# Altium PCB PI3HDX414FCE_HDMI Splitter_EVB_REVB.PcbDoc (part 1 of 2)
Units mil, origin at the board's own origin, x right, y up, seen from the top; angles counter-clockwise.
Board outline 3885 x 4772 mil, 4 copper layers (Top Layer, InternalPlane1, InternalPlane2, Bottom Layer); 85 components, 103 nets, 428 pads, 187 vias.
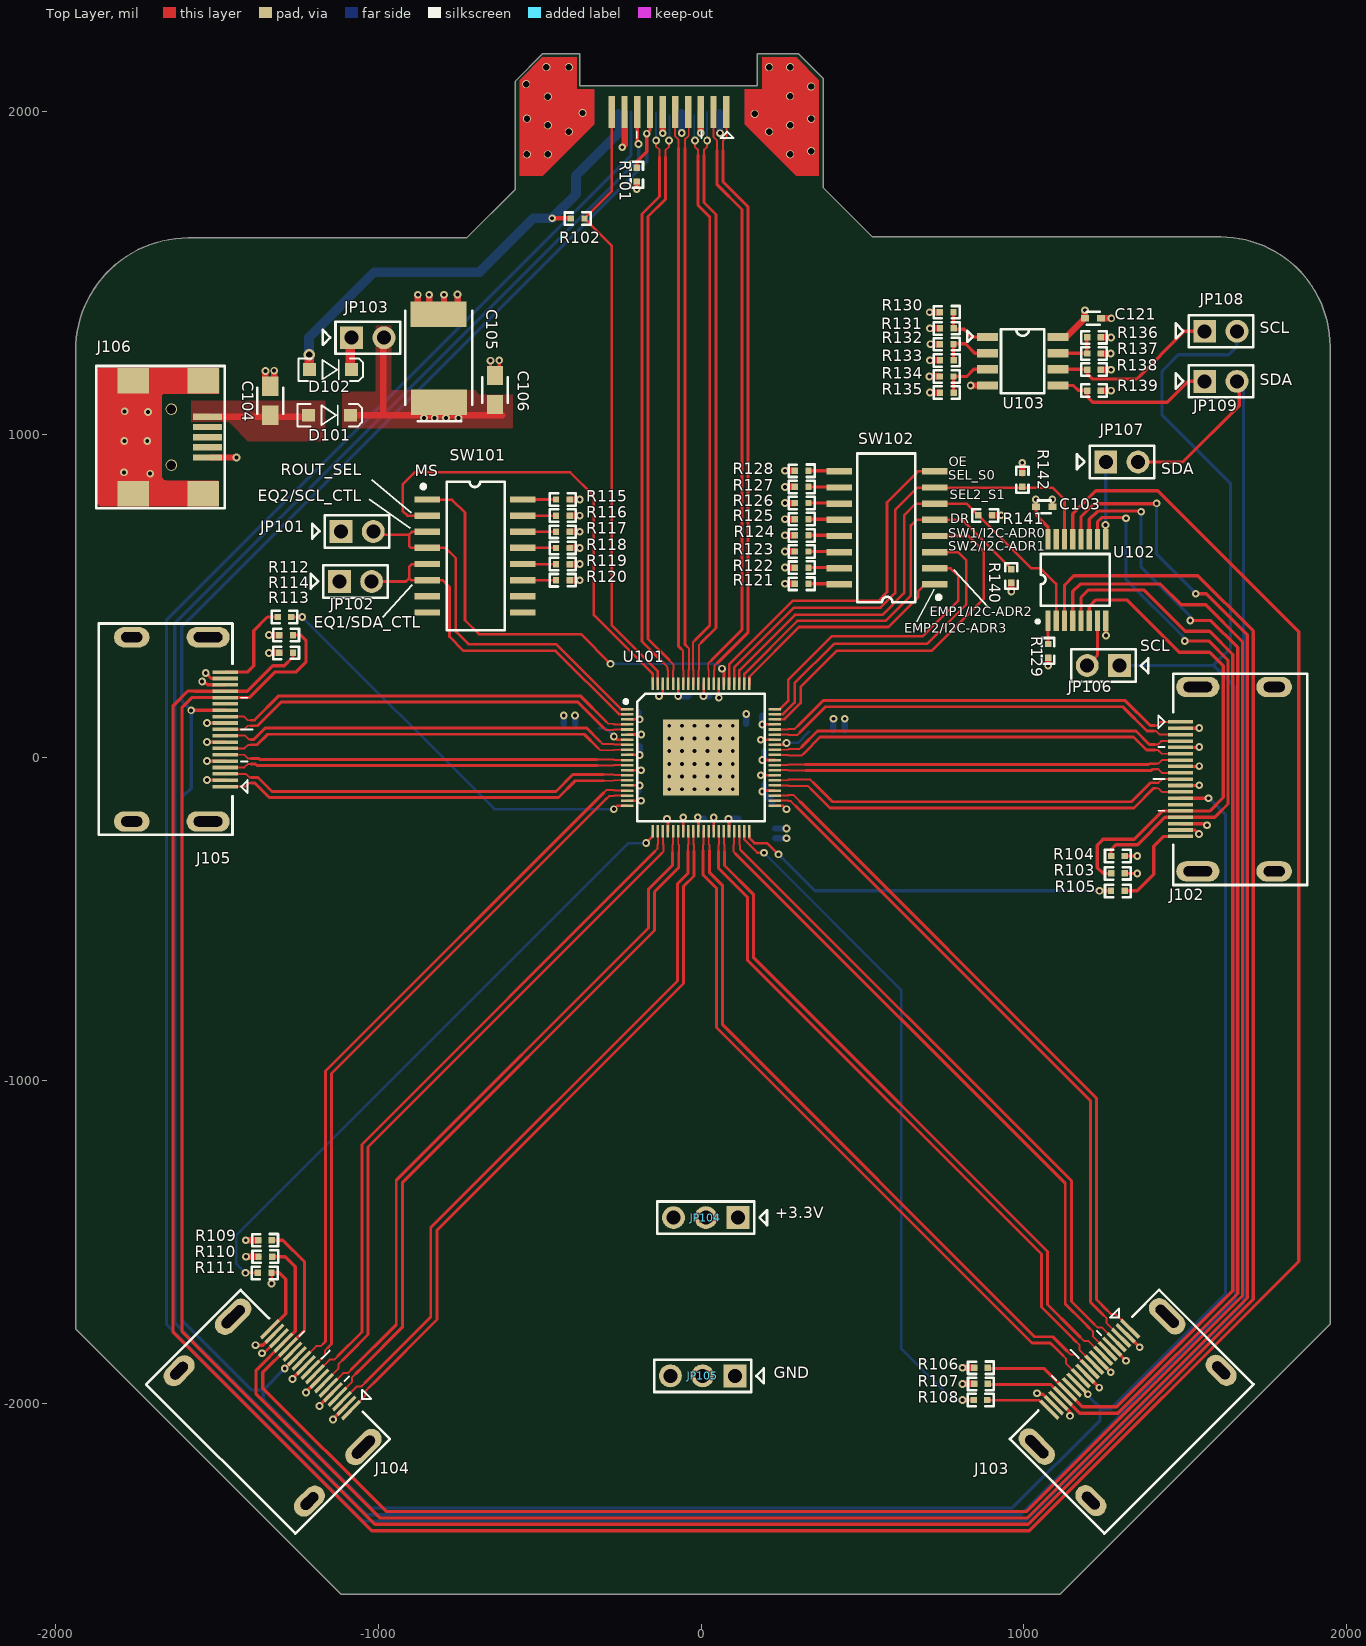
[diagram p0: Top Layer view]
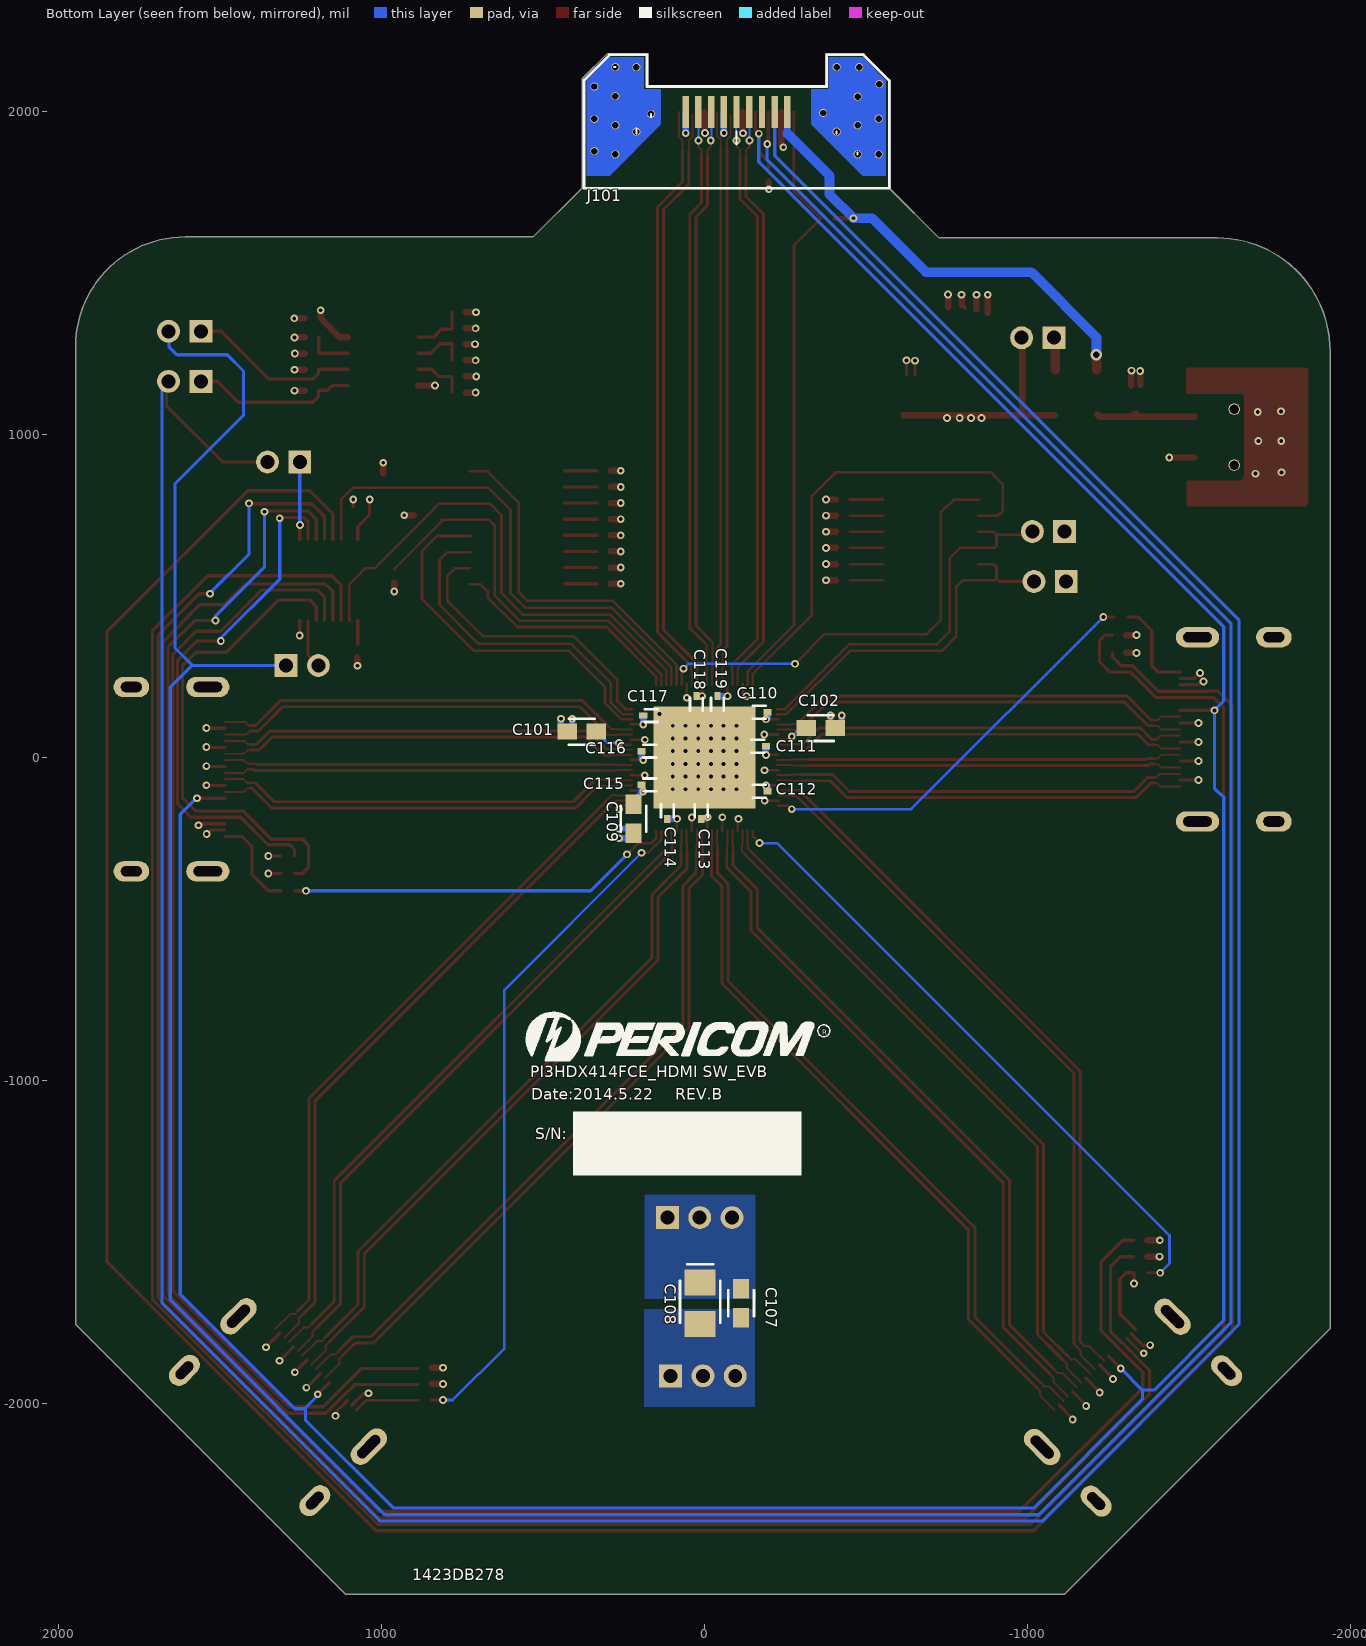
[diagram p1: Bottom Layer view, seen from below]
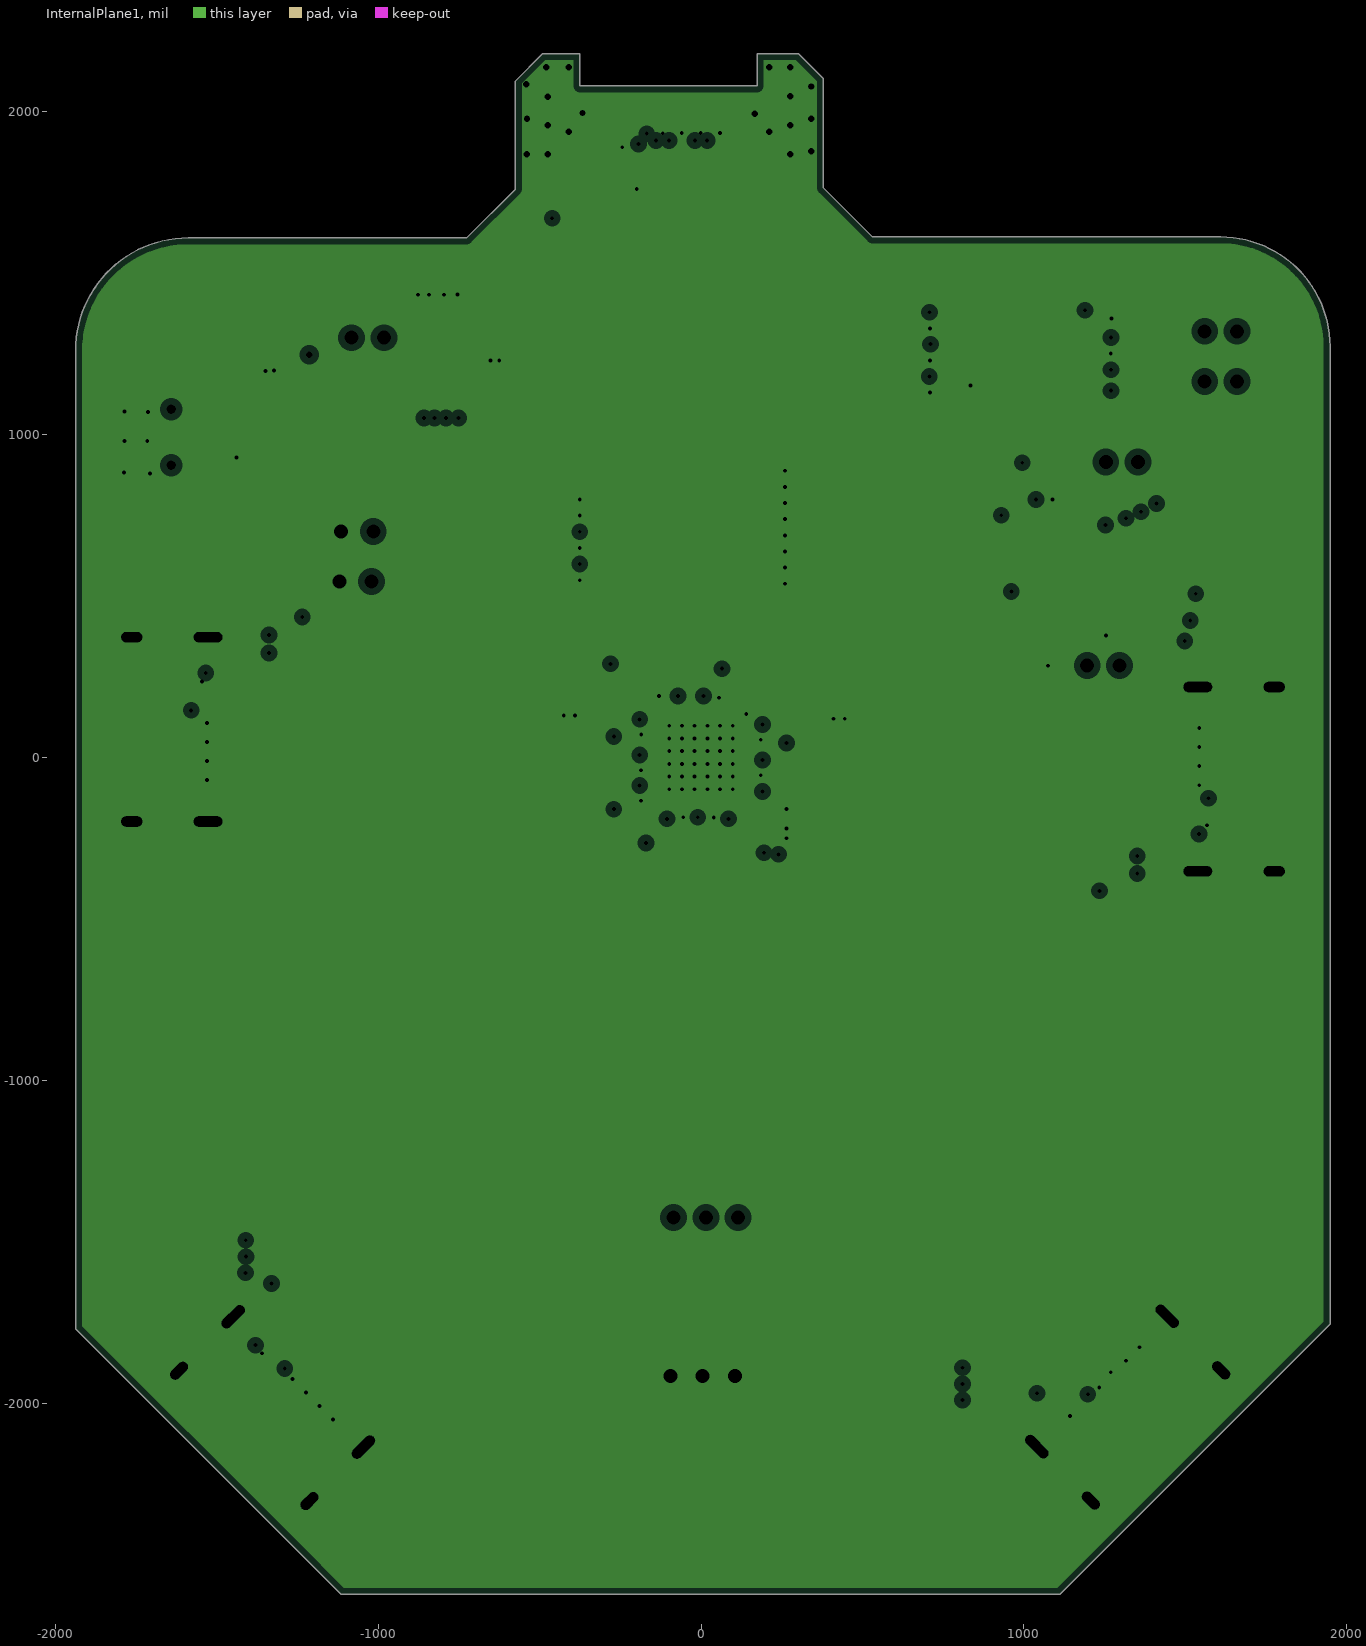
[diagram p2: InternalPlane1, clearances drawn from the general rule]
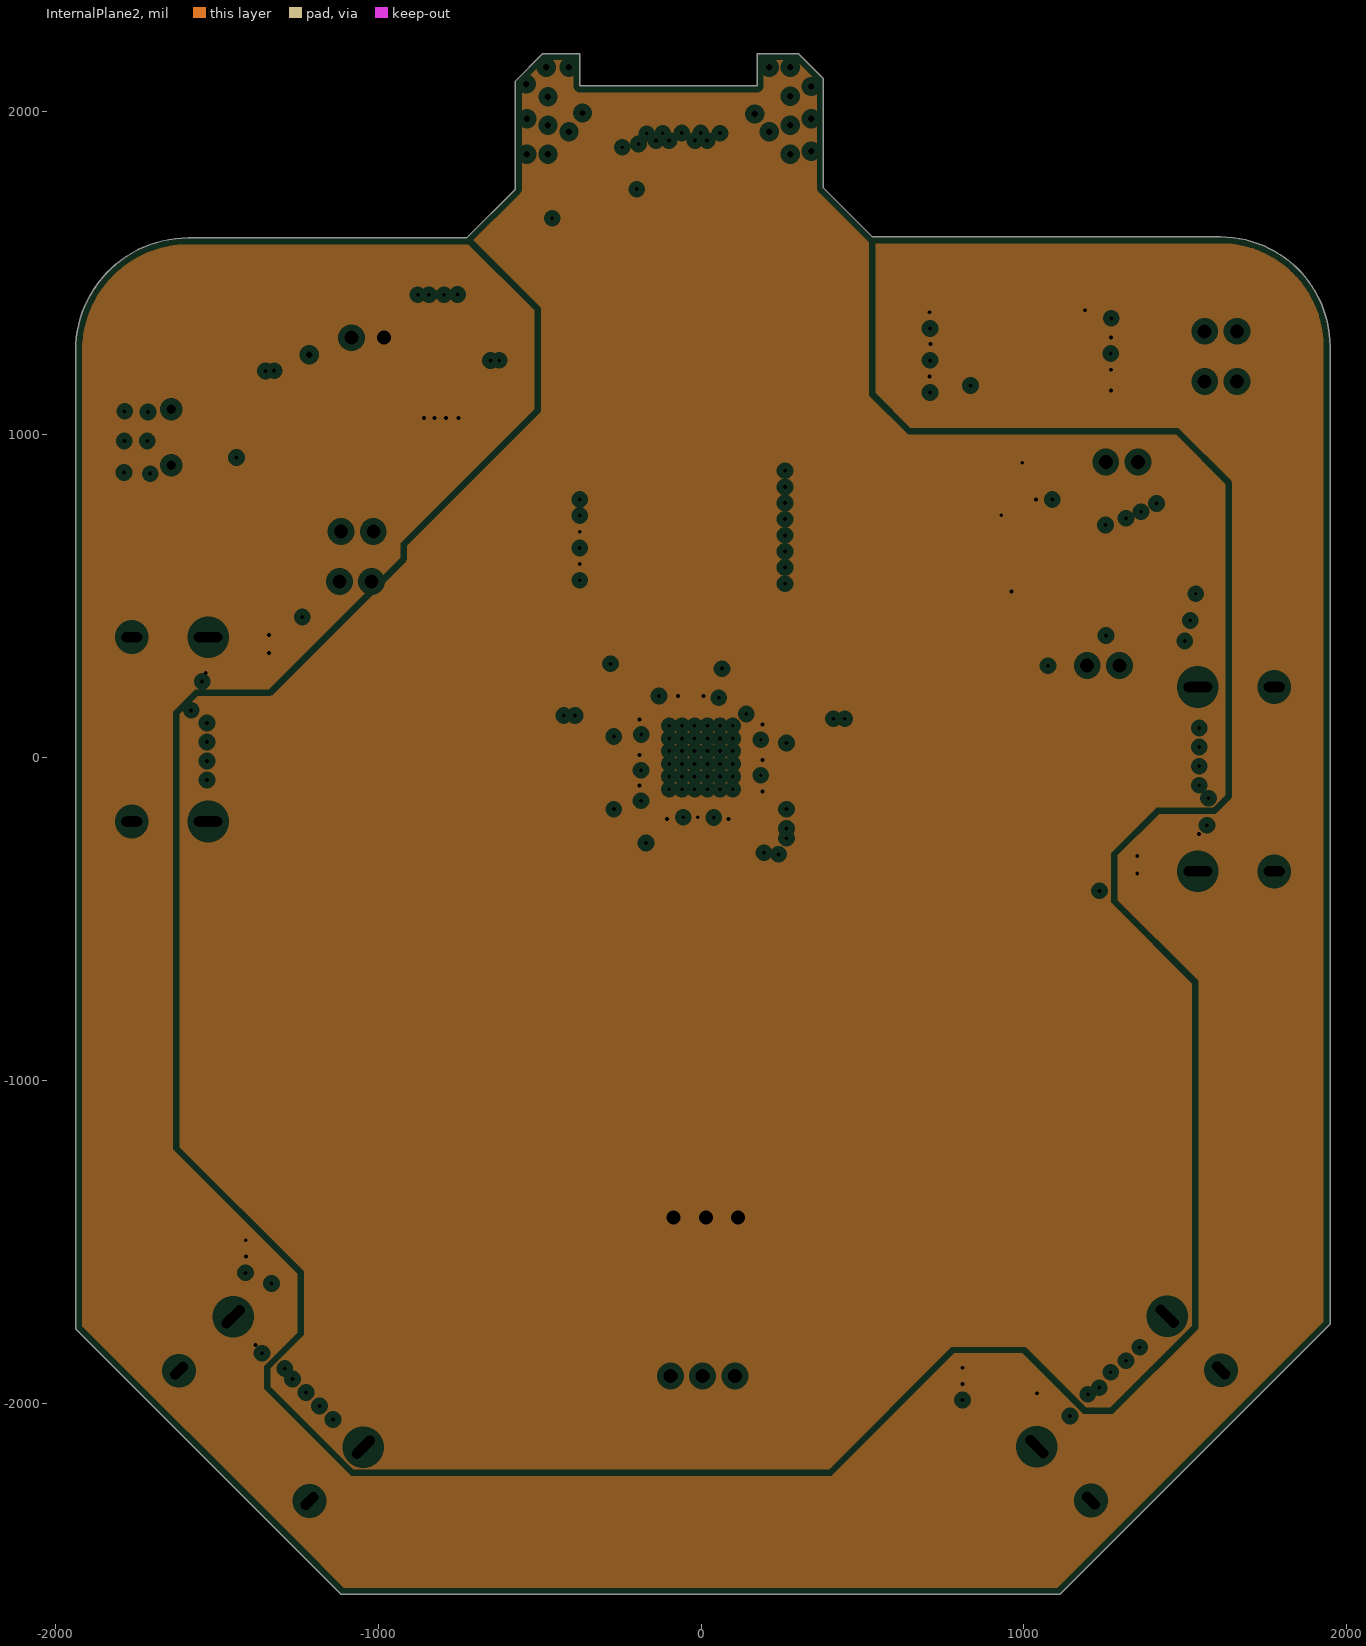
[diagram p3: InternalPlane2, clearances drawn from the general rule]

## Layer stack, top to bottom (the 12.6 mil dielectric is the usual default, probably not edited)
Top Layer: signal copper 1.4
Dielectric: core 12.6, FR-4, Dk 4.8
InternalPlane1: plane copper 1.4, net GND
Dielectric: prepreg 12.6, FR-4, Dk 4.8
InternalPlane2: plane copper 1.4, net +3V3
Dielectric: core 12.6, FR-4, Dk 4.8
Bottom Layer: signal copper 1.4

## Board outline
-1937,-1769 -1269,-2437 -1114,-2592 1111,-2592 1948,-1755 1948,1273 ccw(c1609.03,1273) 1609.03,1611.97 1609.03,1612 531,1612 379,1764 379,2102 301,2180 174,2180 174,2080 -375,2080 -375,2180 -490,2180 -575,2095 -575,1760 -726,1609 -1588,1609 -1588.03,1608.97 ccw(c-1588.03,1260) -1937,1260

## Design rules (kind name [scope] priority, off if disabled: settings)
Clearance [All] p1: gap=5
ComponentClearance [All] p1: gap=0 collisioncheckmode=3 verticalgap=0
HoleSize [All] p1: absolutevalues=TRUE maxlimit=500 minlimit=1 maxpercent=80.000 minpercent=20.000
PlaneClearance [All] p1: clearance=20
PlaneConnect [All] p1: planeconnectstyle=Direct reliefexpansion=20 reliefentries=4 reliefconductorwidth=10 reliefairgap=10
PolygonConnect [All] p1: connectstyle=Direct reliefconductorwidth=10 reliefentries=4 polygonreliefangle="90 Angle"
RoomDefinition PAGE1 [InComponentClass('PAGE1')] p1: confinementstyle=ConfineIn formatcopy=TRUE lockcomponents=FALSE outline -3509,-3526 3364,-3526 3364,3590 -3509,3590
RoomDefinition PAGE2 [InComponentClass('PAGE2')] p2: confinementstyle=ConfineIn formatcopy=TRUE lockcomponents=FALSE outline -3674,-3590 4827,-3590 4827,3583 -3674,3583
RoutingVias [All] p1: holewidth=12 width=20 viastyle="Through Hole" minholewidth=8 minwidth=10 maxholewidth=35 maxwidth=50
SolderMaskExpansion [All] p1: expansion=4
TestPointUsage [All] p1: valid=0 allowmultiple=FALSE
Testpoint [All] p1: side=15 testpointundercomponent=TRUE minsize=40 maxsize=100 preferedsize=60 minholesize=0 maxholesize=40 preferedholesize=32 testpointgrid=1 style=1023 order=0123456789
Width [All] p1: maxlimit=100 minlimit=5 preferedwidth=10
15 further rules are at their usual default settings.

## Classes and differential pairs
component class PAGE2: C103 C104 C105 C106 C107 C108 C109 C110 C111 C112 C113 C114 C115 C116 C117 C118 C119 C120 C121 D101 D102 J106 JP103 JP104 JP105 JP106 JP107 JP108 JP109 R115 R116 R117 R118 R119 R120 R121 R122 R123 R124 R125 R126 R127 R128 R129 R130 R131 R132 R133 R134 R135 R136 R137 R138 R139 R140 R141 R142 SW101 SW102 U102 U103
component class PAGE1: C101 C102 J101 J102 J103 J104 J105 JP101 JP102 R101 R102 R103 R104 R105 R106 R107 R108 R109 R110 R111 R112 R113 R114 U101

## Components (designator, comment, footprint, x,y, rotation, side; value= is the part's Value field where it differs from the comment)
C101 "4.7u 0805" CAP@CC_0805 380,80 r180 bottom
C102 "4.7u 0805" CAP@CC_0805 -360,91 r0 bottom
C103 "0.1u_0402" CC_0402 1063,776 r0 top
C104 "4.7u" CAP@CC_0805 -1334,1105 r90 top
C105 "100u" CAP@CT_7343 -812,1218 r270 top
C106 "1u" CAP@CC_0805 -638,1138 r90 top
C107 "1u 0805" CAP@CC_0805 -113,-1690 r270 bottom
C108 "22u 3528" CAP@CT_3528 14,-1690 r270 bottom
C109 "10u_0805" CC_0805 220,-190 r270 bottom
C110 "0.1u_0402" CC_0402 -170,140 r0 bottom
C111 "0.1u_0402" CC_0402 -165,35 r0 bottom
C112 "0.1u_0402" CC_0402 -170,-105 r0 bottom
C113 "0.1u_0402" CC_0402 10,-165 r90 bottom
C114 "0.1u_0402" CC_0402 115,-165 r90 bottom
C115 "0.1u_0402" CC_0402 170,-85 r180 bottom
C116 "0.1u_0402" CC_0402 170,20 r180 bottom
C117 "0.1u_0402" CC_0402 165,130 r180 bottom
C118 "0.1u_0402" CC_0402 25,165 r270 bottom
C119 "0.1u_0402" CC_0402 -40,165 r270 bottom
C121 "0.1u_0402" CC_0402 1214,1360 r0 top
D101 "B0520LW" D@SOD-123 -1150,1060 r0 top
D102 "B0520LW" D@SOD-123 -1147,1201 r0 top
J101 "CON_HDMI_Plug" CON_HDMI_Plug -99,2038 r270 bottom locked
J102 "CON_HDMI_Recept" CON_HDMI_Recept 1496,110 r90 top locked
J103 "CON_HDMI_Recept" CON_HDMI_Recept 1337,-1777 r45 top locked
J104 "CON_HDMI_Recept" CON_HDMI_Recept -1092,-2029 r315 top locked
J105 "CON_HDMI_Recept" CON_HDMI_Recept -1484,-90 r270 top locked
J106 "CON_USB2.0_MiniB_SMT" CON_USB2.0_MiniB_SMT -1847,992 r0 top
JP101 "2x1 Pin Header" "2x1 Pin Header" -1115,700 r0 top
JP102 "2x1 Pin Header" "2x1 Pin Header" -1120,545 r0 top
JP103 "2x1 Pin Header" "2x1 Pin Header" -1082,1300 r0 top
JP104 "3x1 Pin Header" "3x1 Pin Header" 115,-1425 r180 top
JP105 "3x1 Pin Header" "3x1 Pin Header" 105,-1915 r180 top
JP106 "2x1 Pin Header" "2x1 Pin Header" 1296,285 r180 top
JP107 "2x1 Pin Header" "2x1 Pin Header" 1253.57,915 r0 top
JP108 "2x1 Pin Header" "2x1 Pin Header" 1560,1320 r0 top
JP109 "2x1 Pin Header" "2x1 Pin Header" 1560,1165 r0 top
R101 "100k_0402" R_0402 -199,1805 r270 top
R102 "1k_0402" R_0402 -382,1669 r180 top
R103 "2K2" RES@R_0402 1291,-359 r0 top
R104 "2K2" RES@R_0402 1291,-305 r0 top
R105 "10k_0402" R_0402 1291,-413 r180 top
R106 "2K2" RES@R_0402 866.95,-1889.97 r180 top
R107 "2K2" RES@R_0402 866.95,-1939.97 r180 top
R108 "10k_0402" R_0402 865.95,-1989.97 r180 top
R109 "2K2" RES@R_0402 -1350,-1495 r180 top
R110 "2K2" RES@R_0402 -1349,-1546 r180 top
R111 "10K" RES@R_0402 -1351,-1596 r180 top
R112 "10k_0402" R_0402 -1290,435 r180 top
R113 "2k2_0402" R_0402 -1285,324 r0 top
R114 "2k2_0402" R_0402 -1285,379 r0 top
R115 "4k7_0402" R_0402 -428,799 r0 top
R116 "4k7_0402" R_0402 -428,749 r0 top
R117 "4k7_0402" R_0402 -428,699 r0 top
R118 "4k7_0402" R_0402 -428,649 r0 top
R119 "4k7_0402" R_0402 -428,599 r0 top
R120 "4k7_0402" R_0402 -428,549 r0 top
R121 "4k7_0402" R_0402 312,538 r180 top
R122 "4k7_0402" R_0402 312,588 r180 top
R123 "4k7_0402" R_0402 312,638 r180 top
R124 "4k7_0402" R_0402 312,688 r180 top
R125 "0_0402" R_0402 312,738 r180 top
R126 "0_0402" R_0402 312,788 r180 top
R127 "0_0402" R_0402 312,838 r180 top
R128 "4k7_0402" R_0402 312,888 r180 top
R129 "2k2_0402" R_0402 1075,330 r90 top
R130 "NP/47K" RES@R_0402 761,1379 r180 top
R131 "47K" RES@R_0402 761,1329 r0 top
R132 "NP/47K" RES@R_0402 761,1280 r180 top
R133 "47K" RES@R_0402 761,1230 r0 top
R134 "NP/47K" RES@R_0402 761,1180 r180 top
R135 "47K" RES@R_0402 761,1130 r0 top
R136 "NP/47K" RES@R_0402 1217,1301 r0 top
R137 "47K" RES@R_0402 1217,1251 r180 top
R138 "47K" RES@R_0402 1217,1201 r0 top
R139 "47K" RES@R_0402 1217,1136 r0 top
R140 "10k_0402" R_0402 961,562 r90 top
R141 "10k_0402" R_0402 880,750 r180 top
R142 "10k_0402" R_0402 995,860 r270 top
SW101 "SW_X8_Half_Pitch" SW_X8_Half_Pitch -700,624 r270 top
SW102 "SW_X8_Half_Pitch" SW_X8_Half_Pitch 576,711 r90 top
U101 "PI3HDX414FCE@LQFP80" FC80 0,0 r0 top locked
U102 "PI3USB14-ALE@TSSOP16" TSSOP16 1164,550 r0 top
U103 "AT24C02B" SOIC8 996,1227 r270 top
? "Comment" PSC_LOG 445,-835 r180 bottom

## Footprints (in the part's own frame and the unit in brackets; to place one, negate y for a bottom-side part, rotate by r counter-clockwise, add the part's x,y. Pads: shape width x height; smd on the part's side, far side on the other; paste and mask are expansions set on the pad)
"2x1 Pin Header" [mm] "Pin Header 2x1 Pitch 2.54mm"
  rect 1.8x1.8 hole 1.1: 1(0,0)
  round 1.8 hole 1.1: 2(2.54,0)
  silkscreen extent -2.27,-1.27 3.81,1.27
"3x1 Pin Header" [mm] "Pin Header 3x1 Pitch 2.54mm"
  rect 1.8x1.8 / inner round 1.8 / far side rect 1.8x1.8 hole 1.1: 1(0,0)
  round 1.8 hole 1.1: 2(2.54,0) 3(5.08,0)
  silkscreen extent -2.27,-1.27 6.35,1.27
CAP@CC_0805 [mil]
  rect 60x50 smd: 1(-45,0) 2(45,0)
  silkscreen extent -40,-40 40,40
CAP@CT_3528 [mil]
  rect 80x95 smd: 1(-64,0) 2(64,0)
  silkscreen extent -121,-62 60,62
CAP@CT_7343 [mm]
  rect 2x4.4 smd: 1(3,0) 2(-3.926,-0.011)
  silkscreen extent -4.19,-2.64 4.5,2.62
CC_0402 [mil]
  rect 25x20 smd: 1(-25,0) 2(25,0)
  silkscreen extent -20,-20 20,20
CC_0805 [mil]
  rect 60x50 smd: 1(-45,0) 2(45,0)
  silkscreen extent -40,-40 40,40
CON_HDMI_Plug [mm]
  rect 2.5x0.5 smd far side: 1(1,-4.5) 3(1,-3.5) 5(1,-2.5) 7(1,-1.5) 9(1,-0.5) 11(1,0.5) 13(1,1.5) 15(1,2.5) 17(1,3.5) 19(1,4.5)
  rect 2.5x0.5 smd: 2(1,-4) 4(1,-3) 6(1,-2) 8(1,-1) 10(1,0) 12(1,1) 14(1,2) 16(1,3) 18(1,4)
  round 0.635 hole 0.508: 20(-2.54,-9.525) 20(-2.54,-7.874) 20(-2.54,7.874) 20(-2.54,9.652) 20(-1.21,11.24) 20(-1.016,-11.176) 20(-0.254,-9.525) 20(-0.22,9.525) 20(1.067,6.807) 20(1.143,-6.731) 20(1.51,11.176) 20(1.524,-11.176) 20(2.032,-9.525) 20(2.032,9.525) 20(2.54,-7.874) 20(2.54,7.874) 20(4.064,-11.176) 20(4.318,-9.525) 20(4.318,9.525) 20(4.32,11.18)
  Top Layer region: -0.813,5.893 1.968,5.893 6.013,9.938 6.013,11.728 -1.517,11.728 -1.524,11.735 -3.302,9.957 -3.302,7.264 -0.813,7.264
  Top Layer region: -0.813,-5.944 1.968,-5.944 6.013,-9.989 6.013,-11.779 -1.517,-11.779 -1.524,-11.786 -3.302,-10.008 -3.302,-7.315 -0.813,-7.315
  Bottom Layer region: -0.813,5.893 1.968,5.893 6.013,9.938 6.013,11.728 -1.517,11.728 -1.524,11.735 -3.302,9.957 -3.302,7.264 -0.813,7.264
  Bottom Layer region: -0.813,-5.944 1.968,-5.944 6.013,-9.989 6.013,-11.779 -1.517,-11.779 -1.524,-11.786 -3.302,-10.008 -3.302,-7.315 -0.813,-7.315
  silkscreen extent -3.5,-12 7,12
CON_HDMI_Recept [mm]
  rect 0.28x2 smd: 1(0,0.281) 2(-0.5,0.281) 3(-1,0.281) 4(-1.5,0.281) 5(-2,0.281) 6(-2.5,0.281) 7(-3,0.281) 8(-3.5,0.281) 9(-4,0.281) 10(-4.5,0.281) 11(-5,0.281) 12(-5.5,0.281) 13(-6,0.281) 14(-6.5,0.281) 15(-7,0.281) 16(-7.5,0.281) 17(-8,0.281) 18(-8.5,0.281) 19(-9,0.281)
  oval 1.6x3.4 hole 0.8 slot 2.25 at 90 deg: 20(-11.75,-1.08) 21(2.75,-1.08)
  oval 1.6x2.8 hole 0.8 slot 1.65 at 90 deg: 22(-11.75,-7.09) 23(2.75,-7.09)
  silkscreen extent -12.82,-9.68 3.78,2.41
CON_USB2.0_MiniB_SMT [mm]
  rect 2.3x0.5 smd: 1(8.1,1.6) 2(8.1,0.8) 3(8.1,0) 4(8.1,-0.8) 5(8.1,-1.6)
  rect 2.5x2 smd: 5(2.25,-4.45) 5(2.25,4.45) 5(7.75,-4.45) 5(7.75,4.45)
  round 0.9 hole 0.762 unplated: 10(5.25,-2.2) 11(5.25,2.2)
  Top Layer region: 1.58,5.45 -0.35,5.45 -0.438,5.432 -0.513,5.383 -0.562,5.308 -0.58,5.22 -0.58,5.22 -0.58,-5.09 -0.553,-5.224 -0.477,-5.337 -0.364,-5.413 -0.23,-5.44 -0.23,-5.44 8.81,-5.44 8.875,-5.427 8.93,-5.39 8.967,-5.335 8.98,-5.27 8.98,-5.27 8.98,-3.59 8.968,-3.529 8.933,-3.477 8.881,-3.442 8.82,-3.43 8.82,-3.43 4.93,-3.43 4.758,-3.396 4.612,-3.298 4.514,-3.152 4.48,-2.98 4.48,-2.98 4.48,3.17 4.5,3.269 4.556,3.354 4.641,3.41 4.74,3.43 4.74,3.43 8.93,3.43 8.964,3.437 8.994,3.456 9.013,3.486 9.02,3.52 9.02,3.52 9.02,5.26 9.004,5.34 8.958,5.408 8.89,5.454 8.81,5.47 8.81,5.47 1.6,5.47 1.592,5.468 1.586,5.464 1.582,5.458 1.58,5.45
  silkscreen extent -0.65,-5.59 9.45,5.6
D@SOD-123 [mil]
  rect 40x40 smd: 1(-65,0) 2(65,0)
  silkscreen extent -100,-35 100,35
FC80 [mm]
  rect 1x0.2 smd: 1(-5.8,3.8) 2(-5.8,3.4) 3(-5.8,3) 4(-5.8,2.6) 5(-5.8,2.2) 6(-5.8,1.8) 7(-5.8,1.4) 8(-5.8,1) 9(-5.8,0.6) 10(-5.8,0.2) 11(-5.8,-0.2) 12(-5.8,-0.6) 13(-5.8,-1) 14(-5.8,-1.4) 15(-5.8,-1.8) 16(-5.8,-2.2) 17(-5.8,-2.6) 18(-5.8,-3) 19(-5.8,-3.4) 20(-5.8,-3.8) 41(5.8,-3.8) 42(5.8,-3.4) 43(5.8,-3) 44(5.8,-2.6) 45(5.8,-2.2) 46(5.8,-1.8) 47(5.8,-1.4) 48(5.8,-1) 49(5.8,-0.6) 50(5.8,-0.2) 51(5.8,0.2) 52(5.8,0.6) 53(5.8,1) 54(5.8,1.4) 55(5.8,1.8) 56(5.8,2.2) 57(5.8,2.6) 58(5.8,3) 59(5.8,3.4) 60(5.8,3.8)
  rect 0.2x1 smd: 21(-3.8,-5.8) 22(-3.4,-5.8) 23(-3,-5.8) 24(-2.6,-5.8) 25(-2.2,-5.8) 26(-1.8,-5.8) 27(-1.4,-5.8) 28(-1,-5.8) 29(-0.6,-5.8) 30(-0.2,-5.8) 31(0.2,-5.8) 32(0.6,-5.8) 33(1,-5.8) 34(1.4,-5.8) 35(1.8,-5.8) 36(2.2,-5.8) 37(2.6,-5.8) 38(3,-5.8) 39(3.4,-5.8) 40(3.8,-5.8) 61(3.8,5.8) 62(3.4,5.8) 63(3,5.8) 64(2.6,5.8) 65(2.2,5.8) 66(1.8,5.8) 67(1.4,5.8) 68(1,5.8) 69(0.6,5.8) 70(0.2,5.8) 71(-0.2,5.8) 72(-0.6,5.8) 73(-1,5.8) 74(-1.4,5.8) 75(-1.8,5.8) 76(-2.2,5.8) 77(-2.6,5.8) 78(-3,5.8) 79(-3.4,5.8) 80(-3.8,5.8)
  rect 6x6 smd: 81(0,0)
  silkscreen extent -6.03,-5 5,5
PSC_LOG [mil]
  silkscreen extent -107,-103 833,45
R_0402 [mm]
  rect 0.5x0.5 smd: 1(-0.532,-0.001) 2(0.54,-0.001)
  silkscreen extent -1.02,-0.49 1.02,0.49
RES@R_0402 [mm]
  rect 0.5x0.5 smd: 1(-0.532,-0.001) 2(0.54,-0.001)
  silkscreen extent -1.02,-0.49 1.02,0.49
SOIC8 [mm]
  rect 0.65x1.65 smd: 1(-1.905,-2.775) 2(-0.635,-2.775) 3(0.635,-2.775) 4(1.905,-2.775) 5(1.905,2.775) 6(0.635,2.775) 7(-0.635,2.775) 8(-1.905,2.775)
  silkscreen extent -2.5,-4.35 2.5,1.7
SW_X8_Half_Pitch [mm] "CHS-08TA"
  rect 0.5x2 smd: 1(-4.445,-3.75) 2(-3.175,-3.75) 3(-1.905,-3.75) 4(-0.635,-3.75) 5(0.635,-3.75) 6(1.905,-3.75) 7(3.175,-3.75) 8(4.445,-3.75) 9(4.445,3.75) 10(3.175,3.75) 11(1.905,3.75) 12(0.635,3.75) 13(-0.635,3.75) 14(-1.905,3.75) 15(-3.175,3.75) 16(-4.445,3.75)
  silkscreen extent -5.85,-4.22 5.85,2.34
TSSOP16 [mm] "CHS-08TA"
  rect 0.4x1.6 smd: 1(-2.275,-3.204) 2(-1.625,-3.204) 3(-0.975,-3.204) 4(-0.325,-3.204) 5(0.325,-3.204) 6(0.975,-3.204) 7(1.625,-3.204) 8(2.275,-3.204) 9(2.275,3.204) 10(1.625,3.204) 11(0.975,3.204) 12(0.325,3.204) 13(-0.325,3.204) 14(-0.975,3.204) 15(-1.625,3.204) 16(-2.275,3.204)
  silkscreen extent -3.21,-3.4 2.58,2.04

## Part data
C101 C102 C104 C106 C107: library part "CHIP CAP0805"
C103 C110 C111 C112 C113 C114 C115 C116 C117 C118 C119 C121: library part C_0.1u_0402
C105: library part "100UF 7343_1"
C108: library part "22UF 3528"
C109: library part C_10u_0805
D101 D102: library part SchottkyDiode@SOD-123_1
JP101 JP102: library part "2x1 Pin Header_Dup1"
R101 R102 R105 R108 R112 R113 R114 R115 R116 R117 R118 R119 R120 R121 R122 R123 R124 R125 R126 R127 R128 R129 R140 R141 R142: library part R_0402_Dup1
R103 R104 R106 R107 R109 R110 R111 R130 R131 R132 R133 R134 R135 R136 R137 R138 R139: library part "CHIP RES0402_0"
SW101 SW102: library part SW_X8_DIP
U101: library part PI3HDX414FCE@LQFP80_3
U103: library part 24C02@SOIC8

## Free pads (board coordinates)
  rect 314.96x314.96 smd far side: 81(0,0)

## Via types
v1: diameter 24, hole 12, Top Layer to Bottom Layer, tented both sides, 186 vias
v2: diameter 35, hole 20, Top Layer to Bottom Layer, tented both sides, 1 vias

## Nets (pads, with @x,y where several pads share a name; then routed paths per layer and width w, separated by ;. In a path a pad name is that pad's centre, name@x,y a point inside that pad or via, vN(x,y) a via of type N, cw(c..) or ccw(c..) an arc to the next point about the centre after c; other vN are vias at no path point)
+3V3: C103.1 C107.1 C108.1 C109.1 C110.1 C111.1 C112.1 C113.1 C114.1 C115.1 C116.1 C117.1 C118.1 C119.1 JP104.1 JP104.2 JP104.3 R117.2 R119.2 R140.1 R141.1 R142.1 U101.3 U101.10 U101.16 U101.24 U101.30 U101.36 U101.44 U101.50 U101.57 U101.70 U101.75 U102.16 | length 1022.3
  Top Layer w8: U101.16@-228.35,-86.61 v1(-190,-86.61) ; U101.10@-228.35,7.87 v1(-190,7.87) ; U101.3@-228.35,118.11 v1(-190,118.11) ; v1(-105,-190) -102.36,-192.64 U101.24@-102.36,-228.35 ; v1(-70.87,190) U101.75@-70.87,228.35 ; v1(-10,-185) -7.87,-187.13 U101.30@-7.87,-228.35 ; v1(7.87,190) U101.70@7.87,228.35 ; v1(85,-190) 86.61,-191.61 U101.36@86.61,-228.35 ; v1(190,-105) 192.64,-102.36 U101.44@228.35,-102.36 ; v1(190,-7.87) U101.50@228.35,-7.87 ; v1(190,102.36) U101.57@228.35,102.36
  Top Layer w10: v1@1038,799 C103.1@1038,776 1038,751 1074.43,714.57 U102.16@1074.43,676.14
  Top Layer w20: R119.2@-406.73,598.97 v1(-375.72,598.97) ; R117.2@-406.73,698.97 v1(-375.72,698.97) ; R141.1@900.95,750.03 v1(929.97,750.03) ; v1(961,514) R140.1@961.03,541.05 ; R142.1@994.97,880.95 v1(994.97,912.97)
  Bottom Layer w20: C112.1@-195,-105 -195,-91.61 v1(-190,-86.61) ; C110.1@-195,140 -195,123.11 v1(-190,118.11) ; v1(-190,7.87) C111.1@-190,35 ; v1(-70.87,190) C119.1@-40,190 ; v1(-10,-185) -5,-190 C113.1@10,-190 ; v1(7.87,190) C118.1@25,190 ; v1(85,-190) C114.1@115,-190 ; v1(190,-7.87) 195,-2.87 C116.1@195,20 ; v1(190,102.36) C117.1@190,130 ; C115.1@195,-85 195,-100 v1(190,-105) 220,-135 C109.1@220,-145
  other v1: 1037,799
+5V: C105.1 C106.1 C121.1 D101.2 J102.18 J103.18 J104.18 J105.18 JP103.2 R103.2 R104.2 R106.2 R107.2 R109.2 R110.2 R113.1 R114.1 R130.2 R132.2 R134.2 R136.2 R138.2 R139.2 U103.8 | length 1582.4
  Top Layer w10: v1(-1534,262) -1516.65,244.65 J105.18@-1472.94,244.65 ; v1(-1380,-1820) -1357,-1820 -1321.55,-1784.55 J104.18@-1320.81,-1784.55 ; v1@810,-1940 v1(810.06,-1939.94) ; v1(810,-1890) v1@810.06,-1889.94 ; v1@1041,-1969 1044,-1972 1059,-1972 1092.55,-2005.55 J103.18@1092.55,-2005.81 ; R103.2@1312.27,-359.03 v1(1350.97,-359.03) ; R104.2@1312.27,-305.03 v1(1350.97,-305.03) ; J102.18@1484.94,-224.65 1529.65,-224.65 v1(1542,-237)
  Top Layer w19.68: D101.2@-1085,1060 -984,1060 ; JP103.2@-984,1291 -984,1060 ; -616,1060 -638,1060 -751,1060 -790,1060 -812,1060 -825,1060 -858,1060 -984,1060
  Top Layer w20: v1(-1409.97,-1494.97) R109.2@-1371.27,-1494.97 ; v1(-1408.97,-1545.97) R110.2@-1370.27,-1545.97 ; v1(-1337.65,323.97) R113.1@-1305.95,323.97 ; v1(-1337.65,378.97) R114.1@-1305.95,378.97 ; v1(707.06,1180.03) R134.2@739.73,1180.03 ; v1(708.03,1379.03) R130.2@739.73,1379.03 ; v1(711.03,1280.03) R132.2@739.73,1280.03 ; v1(810.06,-1939.94) R107.2@845.68,-1939.94 ; v1@810.06,-1889.94 R106.2@845.68,-1889.94 ; U103.8@1105.25,1302 1131,1302 C121.1@1189,1360 v1(1189,1385) ; R139.2@1238.27,1135.97 v1(1269.97,1135.97) ; R138.2@1238.27,1200.97 v1(1269.97,1200.97) ; R136.2@1238.27,1300.97 v1(1269.97,1300.97)
  other v1: 1040.86,-1968.86 -858,1051 -825,1051 -790,1051 -751,1051
+5V_S: D102.1 J101.18 R102.2 | length 1477.3
  Top Layer w15: v1(-461,1670) -404.24,1670 R102.2@-403.27,1669.03
  Top Layer w30: D102.1@-1214.09,1201.05 v2(-1213,1247)
  Bottom Layer w19.68: -256.48,1932.52 J101.18@-256.48,1998.63
  Bottom Layer w30: v2@-1214,1247 -1214,1301 -1012,1503 -686,1503 -519,1670 v1(-461,1670) -387.01,1743.99 -387.01,1801.99 -256.48,1932.52
+5V_USB: C104.1 D101.1 J106.1 | length 304
  Top Layer w19.68: J106.1@-1517.1,1054.99 -1334,1054.99 -1223.01,1054.99 -1216.5,1061.5 D101.1@-1216,1062
A0: R130.1 R131.2 U103.1 | length 165.8
  Top Layer w10: R130.1@781.95,1379.03 782.27,1378.72 R131.2@782.27,1328.97 785.24,1326 815,1326 839,1302 U103.1@886.75,1302
A1: R132.1 R133.2 U103.2 | length 167.4
  Top Layer w10: R133.2@782.27,1229.97 781.95,1230.28 R132.1@781.95,1280.03 782.92,1281 819,1281 848,1252 U103.2@886.75,1252
A2: R134.1 R135.2 U103.3 | length 164.1
  Top Layer w10: R134.1@781.95,1180.03 781.95,1130.28 R135.2@782.27,1129.97 ; R134.1@781.95,1180.03 823,1180 845,1202 U103.3@886.75,1202
CEC: J101.13 J102.13 J103.13 J104.13 J105.13 R101.1 | length 10278.4
  Top Layer w10: v1@-1578.78,146.22 J105.13@-1472.94,146.22 ; v1(-1289,-1892) J104.13@-1251.21,-1854.21 ; R101.1@-199.03,1825.95 -199.03,1844.97 -168,1876 v1(-168,1932) -158.06,1941.94 J101.13@-158.06,1998.63 ; J103.13@1162.14,-1936.21 1162.21,-1936.21 v1(1198,-1972) ; J102.13@1484.94,-126.22 v1(1571.78,-126.22)
  Bottom Layer w10: v1(-1289,-1892) -1356,-1959 ; -1019.5,-2324.5 -1356,-1988 -1356,-1959 ; -1019.5,-2324 964,-2324 1236,-2052 1236,-2020 1239,-2017 ; v1(-168,1932) -168,1845 -1607.94,405.06 -1607.94,174.94 v1(-1579,146) -1579,-95 -1607.78,-123.78 -1607.78,-1743.22 -1392,-1959 -1356,-1959 ; v1(1198,-1972) 1198,-1976 1239,-2017 ; 1268.51,-2017.49 1268.01,-2017 ; v1@1574.22,-126.22 1624,-176 1624,-1662 1269,-2017 1268.01,-2017 ; 1239,-2017 1268.01,-2017
CK+: J101.10 U101.76 | length 1825.5
  Top Layer w6: -109.5,1859 -109.5,1881.5 -99,1892 v1(-99,1911) ; -98.49,301.49 -84.58,287.58 -84.58,271.43 -86.2,269.8 -86.2,228.35 U101.76@-86.2,224.8
  Top Layer w9: -109.5,1859 -109.5,1729.5 -164,1675 -164,367 -98.49,301.49
  Bottom Layer w6: v1(-99,1911) -97,1913 J101.10@-97,1989
CK+_1: J102.10 U101.46 | length 1318.6
  Top Layer w6: U101.46@224.82,-70.47 228.35,-70.47 269.82,-70.47 271.44,-68.85 338.85,-68.85 347.66,-77.66 ; 1391,-78.35 1391.65,-78.35 ; 1407,-78.35 1416.65,-78.35 1427.83,-67.17 J102.10@1484.94,-67.17
  Top Layer w9: 347.66,-77.66 407,-137 1333,-137 1391.65,-78.35 1407,-78.35
CK+_2: J103.10 U101.32 | length 2200.4
  Top Layer w6: U101.32@24.03,-224.02 24.03,-228.35 24.03,-269.02 25.66,-270.64 25.66,-288 ; 1134.01,-1838.57 1144.44,-1849 1158.45,-1849 J103.10@1203.9,-1894.45
  Top Layer w9: 25.66,-288 25.66,-355.66 67,-397 67,-828 1033,-1794 1089.44,-1794 1112.72,-1817.28 1134.01,-1838.57
CK+_3: J104.10 U101.18 | length 2216.5
  Top Layer w6: J104.10@-1209.45,-1895.9 -1164,-1850.45 -1164,-1836.44 -1154.78,-1827.22 ; -292.27,-127.14 -284.47,-119.34 -270.63,-119.34 -269,-117.72 U101.18@-228.35,-117.72
  Top Layer w9: -1154.78,-1827.22 -1144,-1816.43 -1144,-978.87 -292.27,-127.14
CK+_4: J105.10 U101.5 | length 1320.6
  Top Layer w6: J105.10@-1472.94,87.17 -1414.83,87.17 -1403.65,98.35 -1394,98.35 ; -302.03,92.16 -295.25,85.38 -270.63,85.38 -269,87.01 -228.35,87.01 U101.5@-224,87.01
  Top Layer w9: -1394,98.35 -1373.65,98.35 -1300,172 -381.87,172 -302.03,92.16
CK-: J101.12 U101.77 | length 1833.7
  Top Layer w6: v1(-139,1911) -139,1892 -128.5,1881.5 -128.5,1860 ; -117.2,293.33 -103.58,279.71 -103.58,271.43 -101.95,269.8 -101.95,228.35 U101.77@-101.95,224.8
  Top Layer w9: -128.5,1860 -128.5,1737.37 -183,1682.87 -183,359.13 -117.2,293.33
  Bottom Layer w6: v1(-139,1911) J101.12@-139,1998
CK-_1: J102.12 U101.45 | length 1319.2
  Top Layer w6: U101.45@224.82,-86.22 228.35,-86.22 269.82,-86.22 271.44,-87.85 330.98,-87.85 340.77,-97.64 ; 1400,-95.35 1400.44,-95.35 ; 1407,-95.35 1416.35,-95.35 1427.54,-106.54 J102.12@1484.94,-106.54
  Top Layer w9: 340.77,-97.64 399.13,-156 1340.87,-156 1401.52,-95.35 1407,-95.35
CK-_2: J103.12 U101.31 | length 2216.4
  Top Layer w6: 6.66,-288 6.66,-270.64 8.28,-269.02 8.28,-228.35 U101.31@8.28,-224.02 ; 1120.85,-1852.28 1130.77,-1862.21 1130.77,-1877 J103.12@1176.06,-1922.29
  Top Layer w9: 6.66,-288 6.66,-363.53 48,-404.87 48,-835.87 1025.13,-1813 1081.57,-1813 1099.28,-1830.72 1120.85,-1852.28
CK-_3: J104.12 U101.17 | length 2236.8
  Top Layer w6: J104.12@-1237.29,-1868.06 -1192,-1822.77 -1177.21,-1822.77 -1168.89,-1814.46 ; -301.52,-109.52 -292.34,-100.34 -270.63,-100.34 -269,-101.97 -228.35,-101.97 U101.17@-224,-101.97
  Top Layer w9: -1168.89,-1814.46 -1163,-1808.56 -1163,-971 -301.52,-109.52
CK-_4: J105.12 U101.4 | length 1322
  Top Layer w6: J105.12@-1472.94,126.54 -1414.54,126.54 -1403.35,115.35 -1394,115.35 ; -294,112 -294,111 -287.38,104.38 -270.63,104.38 -269,102.76 -228.35,102.76 U101.4@-224,102.76
  Top Layer w9: -1394,115.35 -1382.43,115.35 ; -1382.43,116.43 -1307.87,191 -374,191 -294,111
D0+: J101.7 U101.73 | length 1784.8
  Top Layer w6: -50.13,1887 -50.13,1913.87 -38,1926 J101.7@-38,1998.63 ; -43.43,344.1 -37.33,338 -37.33,271.43 -38.96,269.8 -38.96,228.35 U101.73@-38.96,224.8
  Top Layer w9: -50.13,1887 -50.13,350.8 -43.43,344.1
D0+_1: J102.7 U101.49 | length 1263.1
  Top Layer w6: U101.49@224.82,-23.23 228.35,-23.23 269.82,-23.23 271.44,-21.6 322,-21.6 ; 1407,-19.3 1415.82,-19.3 1427,-8.11 J102.7@1484.94,-8.11
  Top Layer w9: 322,-21.6 1386.4,-21.6 ; 1388.7,-19.3 1407,-19.3
D0+_2: J103.7 U101.35 | length 2123.3
  Top Layer w6: U101.35@71.28,-224.02 71.28,-228.35 71.28,-269.02 72.9,-270.64 72.9,-291 ; 1174.39,-1795.44 1186.19,-1807.24 1200.21,-1807.24 J103.7@1245.66,-1852.69
  Top Layer w9: 72.9,-291 72.9,-334.9 163,-425 163,-620.13 1073,-1530.13 1073,-1694.05 1154.48,-1775.52 1174.39,-1795.44
D0+_3: J104.7 U101.23 | length 2149.9
  Top Layer w6: J104.7@-1167.69,-1937.66 -1122.24,-1892.21 -1122.24,-1878.19 -1110.53,-1866.48 ; -122.2,-297.2 -116.07,-291.07 -116.07,-270.64 -117.7,-269.02 -117.7,-228.35 U101.23@-117.7,-224.02
  Top Layer w9: -1110.53,-1866.48 -1090.52,-1846.48 -1031,-1786.95 -1031,-1206 -122.2,-297.2
D0+_4: J105.7 U101.9 | length 1288.3
  Top Layer w6: J105.7@-1472.94,28.11 -1413.89,28.11 -1402.7,39.3 -1394,39.3 ; -319,29.13 -312.26,22.39 -270.63,22.39 -269,24.02 -228.35,24.02 U101.9@-224,24.02
  Top Layer w9: -1394,39.3 -1374.7,39.3 -1342,72 -361.87,72 -319,29.13
D0-: J101.9 U101.74 | length 1778.1
  Top Layer w6: J101.9@-81,1990 -81,1925 -69.13,1913.13 -69.13,1885 ; -61.8,336.8 -56.33,331.33 -56.33,271.43 -54.71,269.8 -54.71,228.35 U101.74@-54.71,224.8
  Top Layer w9: -69.13,1887 -69.13,344.13 -61.8,336.8
D0-_1: J102.9 U101.48 | length 1267.2
  Top Layer w6: U101.48@224.82,-38.98 228.35,-38.98 269.82,-38.98 271.44,-40.6 323,-40.6 ; 1407,-36.3 1416.3,-36.3 1427.48,-47.48 J102.9@1484.94,-47.48
  Top Layer w9: 323,-40.6 1394.27,-40.6 1398.57,-36.3 1407,-36.3
D0-_2: J103.9 U101.34 | length 2139.3
  Top Layer w6: 53.9,-290 53.9,-270.64 55.53,-269.02 55.53,-228.35 U101.34@55.53,-224.02 ; 1161.51,-1809.42 1172.53,-1820.45 1172.53,-1835.24 J103.9@1217.82,-1880.53
  Top Layer w9: 53.9,-290 53.9,-342.77 144,-432.87 144,-628 1054,-1538 1054,-1701.92 1141.04,-1788.96 1161.51,-1809.42
D0-_3: J104.9 U101.22 | length 2134.4
  Top Layer w6: J104.9@-1195.53,-1909.82 -1150.24,-1864.53 -1135.45,-1864.53 -1124.79,-1853.87 ; -143.47,-291.6 -135.07,-283.2 -135.07,-270.64 -133.45,-269.02 -133.45,-228.35 U101.22@-133.45,-224.02
  Top Layer w9: -1124.79,-1853.87 -1050,-1779.08 -1050,-1198.13 -143.47,-291.6
D0-_4: J105.9 U101.8 | length 1289.2
  Top Layer w6: J105.9@-1472.94,67.48 -1411.48,67.48 -1400.3,56.3 -1393,56.3 ; -314.22,51.22 -304.39,41.39 -270.63,41.39 -269,39.76 -228.35,39.76 U101.8@-224,39.76
  Top Layer w9: -1393,56.3 -1384.57,56.3 -1349.87,91 -354,91 -314.22,51.22
D1+: J101.4 U101.71 | length 1815.1
  Top Layer w6: U101.71@-7.46,224.8 -7.46,228.35 -7.46,269.8 -5.84,271.43 -5.84,349.16 0.69,355.69 ; 9.5,1865 9.5,1882.5 19,1892 v1(19,1911)
  Top Layer w9: 0.69,355.69 46,401 46,1681.87 9.5,1718.37 9.5,1865
  Bottom Layer w6: v1(19,1911) 19,1998.52 J101.4@19.11,1998.63
D1+_1: J102.4 U101.52 | length 1305.4
  Top Layer w6: U101.52@224.82,24.02 228.35,24.02 269.82,24.02 271.44,25.64 304.64,25.64 312.03,33.03 ; 1406,39.76 1413.76,39.76 1424.94,50.94 J102.4@1484.94,50.94
  Top Layer w9: 312.03,33.03 361,82 1346.87,82 1388.44,40.43 ; 1389,39.76 1406,39.76
D1+_2: J103.4 U101.38 | length 2079.3
  Top Layer w6: U101.38@118.52,-224.02 118.52,-228.35 118.52,-269.02 120.15,-270.64 120.15,-284.15 125.75,-289.75 ; 1216.7,-1754.23 1227.95,-1765.48 1241.97,-1765.48 J103.4@1287.42,-1810.94
  Top Layer w9: 125.75,-289.75 1147,-1311 1147,-1684.53 1216.7,-1754.23
D1+_3: J104.4 U101.26 | length 2193.9
  Top Layer w6: J104.4@-1125.94,-1979.42 -1080.48,-1933.97 -1080.48,-1919.95 -1069.05,-1908.52 ; U101.26@-70.46,-224.02 -70.46,-228.35 -70.46,-269.02 -68.83,-270.64 -68.83,-294
  Top Layer w9: -1069.05,-1908.52 -1048.77,-1888.23 -925,-1764.47 -925,-1316.87 -144,-535.87 -144,-416 -68.83,-340.83 -68.83,-294
D1+_4: J105.4 U101.12 | length 1256.4
  Top Layer w6: J105.4@-1472.94,-30.94 -1413.94,-30.94 -1402.76,-19.76 -1394,-19.76 ; -320,-24.85 -270.63,-24.85 -269,-23.23 -228.35,-23.23 U101.12@-224,-23.23
  Top Layer w9: -1394,-19.76 -1380.11,-19.76 -1375.02,-24.85 -320,-24.85
D1-: J101.6 U101.72 | length 1806.2
  Top Layer w6: U101.72@-23.21,224.8 -23.21,228.35 -23.21,269.8 -24.84,271.43 -24.84,357.03 -17.65,364.22 ; v1(-19,1911) -19,1892 -9.5,1882.5 -9.5,1866
  Top Layer w9: -17.65,364.22 27,408.87 27,1674 -9.5,1710.5 -9.5,1866
  Bottom Layer w6: J101.6@-21,1989 -21,1913 v1(-19,1911)
D1-_1: J102.6 U101.51 | length 1305.4
  Top Layer w6: U101.51@224.82,8.27 228.35,8.27 269.82,8.27 271.44,6.64 312.51,6.64 318.61,12.74 ; 1406,22.76 1415.24,22.76 1426.43,11.57 J102.6@1484.94,11.57
  Top Layer w9: 318.61,12.74 368.87,63 1339,63 1379.24,22.76 1406,22.76
D1-_2: J103.6 U101.37 | length 2095.3
  Top Layer w6: U101.37@102.77,-224.02 102.77,-228.35 102.77,-269.02 101.15,-270.64 101.15,-292.02 107.15,-298.02 ; 1203.4,-1767.8 1214.29,-1778.69 1214.29,-1793.48 J103.6@1259.58,-1838.77
  Top Layer w9: 107.15,-298.02 1128,-1318.87 1128,-1692.4 1182.8,-1747.2 1203.4,-1767.8
D1-_3: J104.6 U101.25 | length 2178.4
  Top Layer w6: J104.6@-1153.77,-1951.58 -1108.48,-1906.29 -1093.69,-1906.29 -1082.07,-1894.67 ; -87.83,-293 -87.83,-270.64 -86.2,-269.02 -86.2,-228.35 U101.25@-86.2,-224.02
  Top Layer w9: -1082.07,-1894.67 -944,-1756.6 -944,-1309 -163,-528 -163,-408.13 -87.83,-332.96 -87.83,-293
D1-_4: J105.6 U101.11 | length 1255.3
  Top Layer w6: J105.6@-1472.94,8.43 -1414.43,8.43 -1403.24,-2.76 -1394,-2.76 ; -322,-5.85 -270.63,-5.85 -269,-7.48 -228.35,-7.48 U101.11@-224,-7.48
  Top Layer w9: -1394,-2.76 -1369.75,-2.76 ; -1369.75,-3.25 -1367.15,-5.85 -322,-5.85
D2+: J101.1 U101.68 | length 1854.7
  Top Layer w6: U101.68@39.78,224.8 39.78,228.35 39.78,269.8 41.41,271.43 41.41,283.4 51.66,293.66 ; 67.98,1879 67.98,1910 79,1921.02 J101.1@79,1998.63
  Top Layer w9: 51.66,293.66 146,388 146,1705 67.98,1783.02 67.98,1879
D2+_1: J102.1 U101.56 | length 1333.6
  Top Layer w6: U101.56@224.82,87.01 228.35,87.01 269.82,87.01 271.44,88.63 290.63,88.63 300.04,98.04 ; 1404,98.82 1411.81,98.82 1423,110 J102.1@1484.94,110
  Top Layer w9: 300.04,98.04 378,176 1314,176 1391.19,98.82 1404,98.82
